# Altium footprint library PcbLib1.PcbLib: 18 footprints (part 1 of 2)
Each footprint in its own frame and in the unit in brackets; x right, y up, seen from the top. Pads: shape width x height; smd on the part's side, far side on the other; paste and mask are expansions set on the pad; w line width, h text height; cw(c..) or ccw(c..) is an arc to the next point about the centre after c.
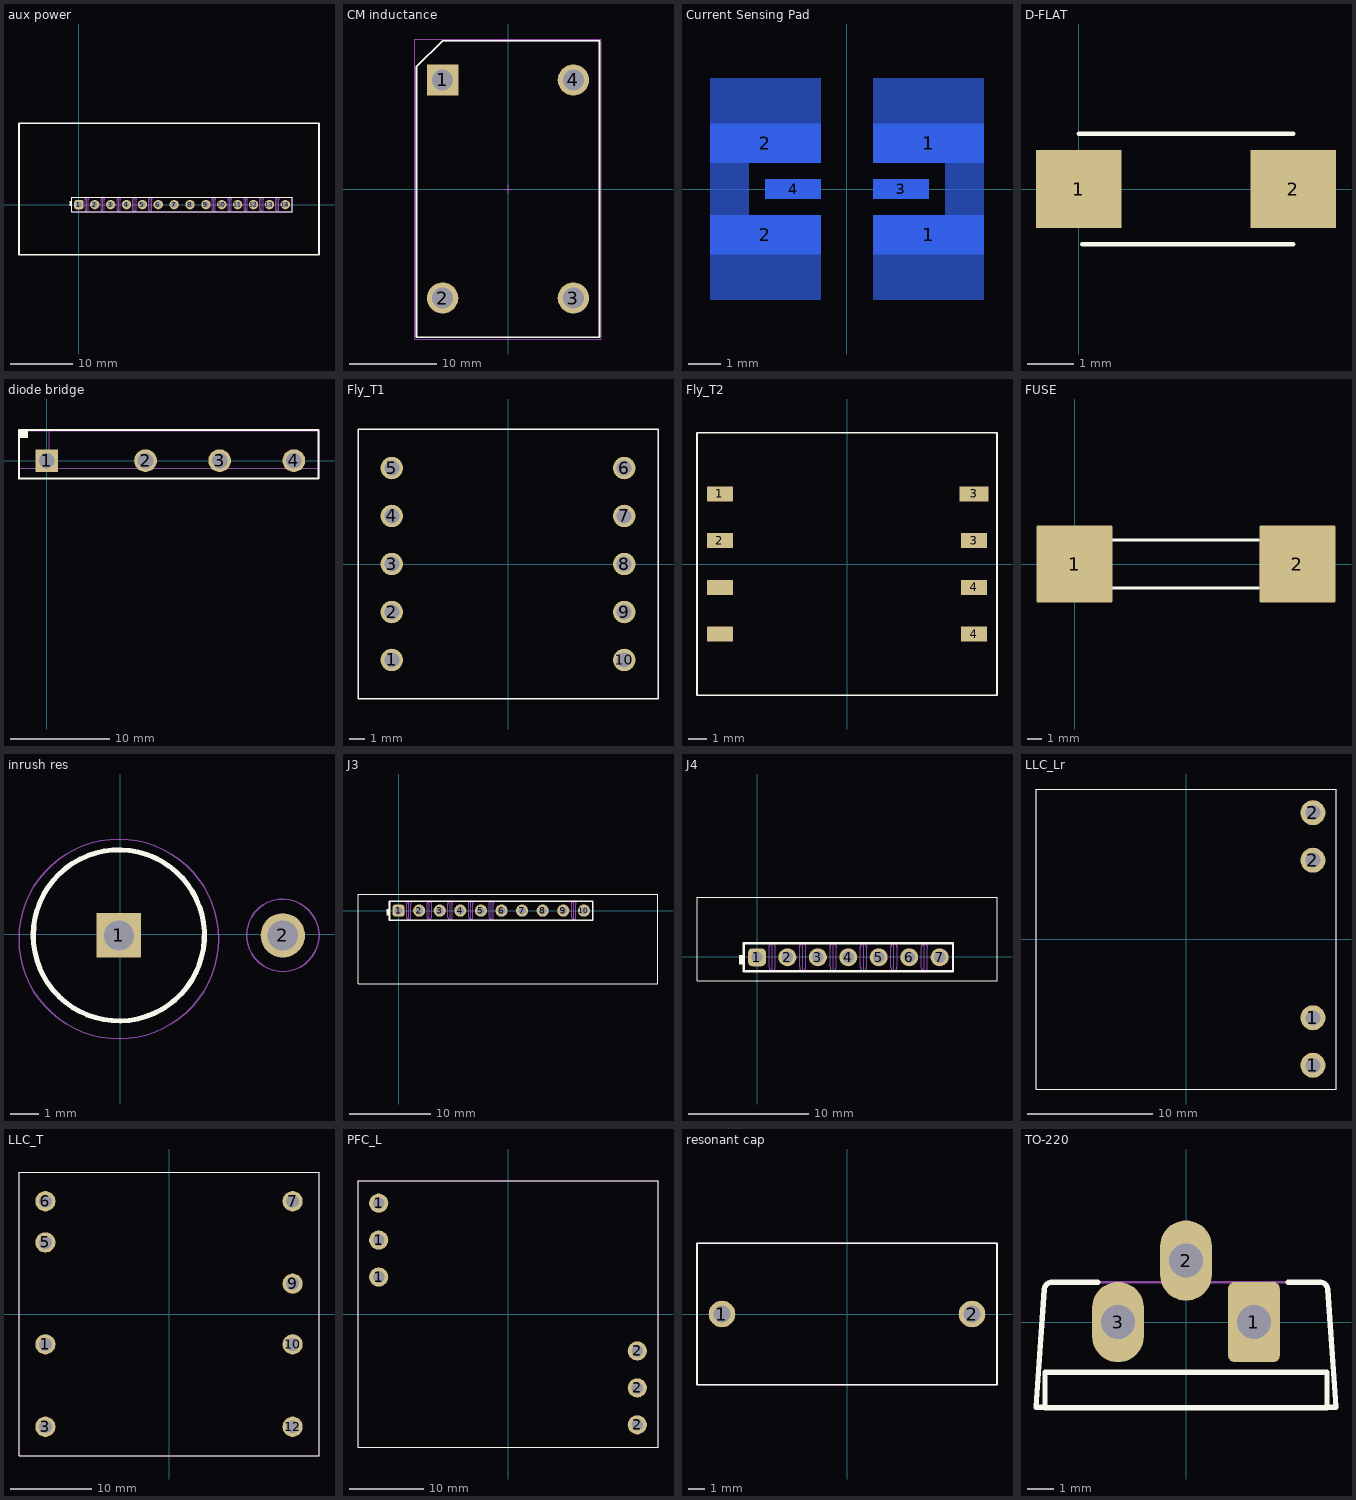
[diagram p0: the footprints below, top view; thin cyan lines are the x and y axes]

## aux power [mm]
pads (14):
  rrect50% 1.5x1.5 hole 0.94: 1(0,0)
  round 1.5 hole 0.94: 2(2.54,0) 3(5.08,0) 4(7.62,0) 5(10.16,0) 6(12.7,0) 7(15.24,0) 8(17.78,0) 9(20.32,0) 10(22.86,0) 11(25.4,0) 12(27.94,0) 13(30.48,0) 14(33.02,0)
Top Overlay:
  rectangle: -1.49,-0.2 -1.117,0.6
  lines w0.2: -1.117,-1.168 -1.117,-0.787 -1.117,0.787 -1.117,1.168 -0.316,1.168 34.139,1.168 34.139,0.787 34.139,-0.787 34.139,-1.168 -1.117,-1.168
  lines w0.254: -9.585,-8 38.415,-8 38.415,13 -9.585,13 -9.585,-8
Mechanical 5:
  drawing of 7090 lines, arcs and shapes, not listed
  text ".Designator" at 14.91,0.4 h0.89

## CM inductance [mm]
pads (4):
  rect 3.6x3.6 hole 2.4: 1(-7.5,12.5)
  round 3.6 hole 2.4: 2(-7.5,-12.5) 3(7.5,-12.5) 4(7.5,12.5)
Top Overlay:
  lines w0.2: -10.5,-17 10.5,-17 10.5,17 -7.5,17 -10.5,14 -10.5,-17
Mechanical 13:
  lines w0.1: -10.5,-17 -10.5,14 -7.5,17 10.5,17 10.5,-17 -10.5,-17
Mechanical 15:
  lines w0.05: -0.5,0 0.5,0 ; 0,-0.5 0,0.5 ; -10.7,-17.2 -10.7,17.2 10.7,17.2 10.7,-17.2 -10.7,-17.2
3D body "7448051804_36x23x36_without pins.stp": height 31.09, standoff -4.9, extent -10.3,-16.069 10.3,16.071

## Current Sensing Pad [mm] "Current Sensing Pad for 2512"
pads (6):
  rect 3.4x1.2 smd far side: 1(2.501,-1.4) 1(2.501,1.4) 2(-2.499,-1.4) 2(-2.499,1.4)
  rect 1.7x0.6 smd far side: 3(1.651,0) 4(-1.649,0)
Bottom Layer:
  rectangle: -4.199,2 -0.799,3.4
  rectangle: 0.801,2 4.201,3.4
  rectangle: 0.801,-3.4 4.201,-2
  rectangle: -4.199,-3.4 -0.799,-2
  rectangle: -4.199,-0.8 -2.999,0.8
  rectangle: 3.001,-0.8 4.201,0.8
  lines w0.254: 1.651,0 1.701,0
Bottom Overlay:
  lines w0.254: -4.599,-2.3 -4.599,2.3 4.601,2.3 4.601,1.5 4.601,0.3 4.601,-0.5 4.601,-1.025 4.601,-2.075 4.601,-2.3 -4.599,-2.3

## D-FLAT [mm]
pads (2):
  rect 1.85x1.7 smd: 1(0,0) 2(4.65,0)
Top Overlay:
  lines w0.1: 0,1.2 4.65,1.2 ; 0.076,-1.2 4.65,-1.2

## diode bridge [mm]
pads (4):
  rect 2.3x2.3 hole 1.6: 1(-0.003,0)
  round 2.3 hole 1.6: 2(9.997,0) 3(17.497,0) 4(24.997,0)
Top Overlay:
  rectangle: -2.803,2.3 -1.903,3.1
  lines w0.2: -2.803,-1.8 -2.803,3.1 0.697,3.1 27.497,3.1 27.497,-1.8 -2.803,-1.8
Bottom Overlay:
  circle w0.254: c12.35,-15 r1.8
  lines w0.1: -2.803,-8 -2.803,-24 27.497,-24 27.497,-8
Mechanical 6:
  lines w0.1: -2.753,-0.75 -2.753,-1.75 27.547,-1.75 27.547,-0.75 ; -2.753,-0.75 0.247,-0.75 ; -2.753,-0.75 -2.753,3.05 0.247,3.05 ; 0.247,-0.75 27.547,-0.75 ; 0.247,-0.75 0.247,3.05 ; 0.247,3.05 27.547,3.05 27.547,-0.75
  text ".Designator" at 11.197,0.2 h1.02
3D body "GBJ.stp": height 24.3, standoff -4, extent -2.753,-1.75 27.547,3.05

## Fly_T1 [mm]
pads (10):
  round 1.5 hole 1: 1(-7.75,-6.4) 2(-7.75,-3.2) 3(-7.75,0) 4(-7.75,3.2) 5(-7.75,6.4) 6(7.75,6.4) 7(7.75,3.2) 8(7.75,0) 9(7.75,-3.2) 10(7.75,-6.4)
Top Overlay:
  lines w0.1: -10,-9 -10,9 10,9 10,-9 -10,-9

## Fly_T2 [mm]
pads (8):
  rect 1.4x0.8 smd: 1(-6.78,3.735) 2(-6.78,1.245) 3(6.78,1.245) 4(6.78,-3.735) 4(6.78,-1.245) ""(-6.78,-3.735) ""(-6.78,-1.245)
  rect 1.54x0.8 smd: 3(6.78,3.735)
Top Overlay:
  lines w0.1: -8,-7 8,-7 8,7 -8,7 -8,-7

## FUSE [mm]
pads (2):
  rrect3% 5.1x5.2 smd: 1(0,0) 2(15,0)
Top Overlay:
  lines w0.2: 2.54,-1.6 12.395,-1.6 ; 2.565,1.6 12.395,1.6
Mechanical 5:
  lines w0.1: -0.301,-1.59 -0.301,1.59 ; 2.493,-1.59 12.493,-1.59 12.493,1.59 2.493,1.59
  text ".Designator" at 3.327,-0.61 h1.85
3D body: height 3.18, standoff 0, extent 2.493,-1.59 12.493,1.59

## inrush res [mm]
pads (2):
  rect 1.554x1.554 / inner round 1.554 / far side rect 1.554x1.554 hole 1.054: 1(-0.048,-0.033)
  round 1.554 hole 1.054: 2(5.7,-0.033)
Top Overlay:
  lines w0.178: 2.92,0.403 cw(c-0.048,-0.033) 2.92,0.404
Bottom Overlay:
  lines w0.178: -3.048,-0.033 ccw(c-0.048,-0.033) -1.548,-2.631 ; -2.646,1.467 cw(c-0.048,-0.033) -0.048,2.967 ; -0.048,-3.033 ccw(c-0.048,-0.033) 2.55,-1.533 ; 1.452,2.565 cw(c-0.048,-0.033) 2.952,-0.033
Mechanical 5:
  lines w0.127: 2.92,0.403 cw(c-0.048,-0.033) 2.92,0.404
  text ".Designator" at -0.788,0.787 h0.89
Mechanical 15:
  circle w0.05: c-0.048,-0.16 r3.5
  circle w0.05: c5.7,-0.033 r1.27
3D body: height 29, standoff 0, extent -3.048,-3.029 2.952,2.964

## J3 [mm]
pads (10):
  rrect50% 1.5x1.5 hole 0.94: 1(0,0)
  round 1.5 hole 0.94: 2(2.54,0) 3(5.08,0) 4(7.62,0) 5(10.16,0) 6(12.7,0) 7(15.24,0) 8(17.78,0) 9(20.32,0) 10(22.86,0)
Top Overlay:
  rectangle: -1.49,-0.6 -1.117,0.2
  lines w0.1: -5,-9 32,-9 32,2 -5,2 -5,-9
  lines w0.2: -1.117,-1.168 -0.316,-1.168 23.953,-1.168 23.953,-0.787 23.953,0.787 23.953,1.168 -1.117,1.168 -1.117,0.787 -1.117,-0.787 -1.117,-1.168
Mechanical 5:
  drawing of 4263 lines, arcs and shapes, not listed
  text ".Designator" at 12.09,-0.279 h0.89

## J4 [mil]
pads (7):
  rrect50% 59.06x59.06 hole 37: 1(-1,-1)
  round 59.06 hole 37: 2(99,-1) 3(199,-1) 4(299,-1) 5(399,-1) 6(499,-1) 7(599,-1)
Top Overlay:
  rectangle: -59.66,-24.62 -44.96,6.87
  lines w3.94: -197.85,-78.74 787.4,-78.74 787.4,196.85 -196.85,196.85 -196.85,-78.74
  lines w7.87: -44.96,-47 -13.46,-47 643,-47 643,-32 643,30 643,45 -44.96,45 -44.96,30 -44.96,-32 -44.96,-47
Mechanical 5:
  drawing of 4251 lines, arcs and shapes, not listed
  text ".Designator" at 173,-18 h35

## LLC_Lr [mm]
pads (4):
  round 2 hole 1.2: 1(10.15,-10.1) 1(10.15,-6.3) 2(10.15,6.3) 2(10.15,10.1)
Top Overlay:
  lines w0.1: -12,-12 12,-12 12,12 -12,12 -12,-12
Mechanical 5:
  lines w0.1: -12,-12 -12,12 12,12 12,-12 -12,-12
  text ".Designator" at -5.207,-0.127 h1.02

## LLC_T [mm]
pads (8):
  round 2.5 hole 1.6: 1(-15.24,-3.745) 3(-15.24,-13.905) 5(-15.24,8.825) 6(-15.24,13.905) 7(15.24,13.905) 9(15.24,3.745) 10(15.24,-3.745) 12(15.24,-13.905)
Top Overlay:
  lines w0.1: -18.5,-17.5 -18.5,17.5 18.5,17.5 18.5,-17.5 -18.5,-17.5
Mechanical 5:
  lines w0.1: -18.5,-17.5 18.5,-17.5 18.5,17.5 -18.5,17.5 -18.5,-17.5
  text ".Designator" at 5.08,0.203 h1.02

## PFC_L [mm]
pads (6):
  round 2.6 hole 1.6: 1(-17.5,5) 1(-17.5,10) 1(-17.5,15) 2(17.5,-15) 2(17.5,-10) 2(17.5,-5)
Top Overlay:
  lines w0.1: -20.3,-18 -20.3,18 20.3,18 20.3,-18 -20.3,-18
Mechanical 5:
  lines w0.1: -20.3,-18 20.3,-18 20.3,18 -20.3,18 -20.3,-18
  text ".Designator" at -5.893,-0.356 h1.02

## resonant cap [mm]
pads (2):
  round 1.6 hole 1: 1(-7.5,0) 2(7.5,0)
Top Overlay:
  lines w0.1: -9,-4.25 -9,4.25 9,4.25 9,-4.25 -9,-4.25
Mechanical 5:
  lines w0.1: -8.992,-4.242 8.992,-4.242 8.992,4.242 -8.992,4.242 -8.992,-4.242
  text ".Designator" at -4.674,-0.203 h1.02

## TO-220 [mm]
pads (3):
  rrect25% 1.93x3 hole 1.27: 1(2.54,0)
  oval 1.93x3 hole 1.27: 2(0,2.3) 3(-2.54,0)
Top Overlay:
  lines w0.2: -5.27,-3.185 -5.607,-3.185 -5.607,-3.175 ; -5.27,-3.175 -5.607,-3.175 ; -3.302,1.495 -5,1.495 ccw(c-5,1.195) -5.297,1.237 ccw(c-5,1.195) -5.3,1.216 -5.607,-3.175 ; 3.81,1.495 5,1.495 cw(c5,1.195) 5.297,1.237 cw(c5,1.195) 5.299,1.216 5.606,-3.175 ; 5.27,-3.185 5.606,-3.185 5.606,-3.175 ; 5.27,-3.175 5.606,-3.175 ; -5.27,-3.195 5.27,-3.195 5.27,-1.875 -5.27,-1.875 -5.27,-3.195
Mechanical 5:
  lines w0.1: -5.27,-3.185 -5.607,-3.185 -5.607,-3.175 ; -5.27,-3.175 -5.607,-3.175 ; 5.27,-3.185 5.606,-3.185 5.606,-3.175 ; 5.27,-3.175 5.606,-3.175 ; -5.607,-3.175 -5.3,1.216 cw(c-5,1.195) -5.297,1.237 cw(c-5,1.195) -5,1.495 5,1.495 cw(c5,1.195) 5.297,1.237 cw(c5,1.195) 5.299,1.216 5.606,-3.175 ; -5.27,-3.195 5.27,-3.195 5.27,-1.875 -5.27,-1.875 -5.27,-3.195
  text ".Designator" at 1.524,0.508 h1.02
3D body "TO-220AB.stp": height 19.42, standoff -3.88, extent -5.607,-3.195 5.606,1.495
